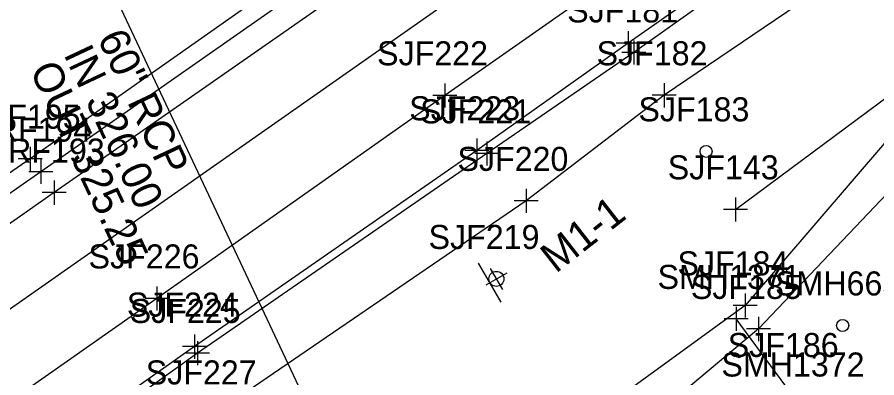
# Model space of a CAD drawing. Extents: x 941041 to 969446, y 397014 to 416764.
# Drawn here: x 953374.6 to 953517.5, y 404241 to 404301 of the extents above; entities that cross this region are included whole.
import ezdxf

# ---------------------------------------------------------------- set-up
doc = ezdxf.new("R2010")
doc.units = 0
for name, color, linetype in [('SURVEY - DRAINAGE - Area Shapes', 7, 'Continuous'), ('SURVEY - DRAINAGE - Pipes and Culverts', 7, 'Continuous'), ('SURVEY - DRAINAGE - Pipes and Culverts Text', 7, 'Continuous'), ('SURVEY - DTM - Breaklines', 7, 'Continuous'), ('SURVEY - DTM - Breaklines - Points - Locators', 7, 'Continuous'), ('SURVEY - DTM - Breaklines - Points - Numbers', 7, 'Continuous'), ('SURVEY - DTM - Spot Points - Locators', 7, 'Continuous'), ('SURVEY - DTM - Spot Points - Point Numbers', 7, 'Continuous'), ('SURVEY - TRAFFIC CONTROL - Signs - Points - Locators', 7, 'Continuous'), ('SURVEY - TRAFFIC CONTROL - Signs - Points - Numbers', 7, 'Continuous'), ('SURVEY - TRAFFIC CONTROL - Signs and Devices with Text', 7, 'Continuous'), ('SURVEY - TRANSPORTATION - Features', 7, 'Continuous'), ('SURVEY - TRANSPORTATION - Features - Points - Locators', 7, 'Continuous'), ('SURVEY - TRANSPORTATION - Features - Points - Numbers', 7, 'Continuous'), ('SURVEY - TRANSPORTATION - Roads', 7, 'Continuous'), ('SURVEY - TRANSPORTATION - Roads - Points - Locators', 7, 'Continuous'), ('SURVEY - TRANSPORTATION - Roads - Points - Numbers', 7, 'Continuous'), ('SURVEY - VEGETATION - Features - Points - Locators', 7, 'Continuous'), ('SURVEY - VEGETATION - Features - Points - Numbers', 7, 'Continuous'), ('SURVEY - VEGETATION - Features with Text', 7, 'Continuous')]:
    doc.layers.add(name, color=color, linetype=linetype)

msp = doc.modelspace()

# ---------------------------------------------------------------- linework, layer by layer
at = {"layer": 'SURVEY - DRAINAGE - Area Shapes'}
msp.add_lwpolyline([(954050.98, 404130.56), (953837.45, 404341.16), (953706.36, 404460.47), (953686.21, 404471.93), (953450.22, 404306.36), (952524.78, 403657.05)], dxfattribs=at)
at = {"layer": 'SURVEY - DRAINAGE - Pipes and Culverts'}
msp.add_line((953427.04, 404227.58), (953345.04, 404402.16), dxfattribs=at)
at = {"layer": 'SURVEY - DTM - Breaklines'}
for points in [[(953930.5, 404594.79), (953899.28, 404573.09), (953853.92, 404543.05), (953843.46, 404534.82), (953797.38, 404504.4), (953755.05, 404474.71), (953712.83, 404445.46), (953669.81, 404415.98), (953611.07, 404372.77), (953586.59, 404349.95), (953558.91, 404313.55), (953497.8, 404249.13), (953473.51, 404228.83), (953446.86, 404209.01), (953450.01, 404200.36), (953460.86, 404196.95), (953466.73, 404189.97)], [(953577.48, 404348.57), (953495.56, 404253.05), (953464.32, 404230.29), (953444.07, 404217.87), (953439.28, 404212.03), (953436.75, 404213.93), (953439.45, 404218.19), (953433.81, 404222.03), (953433.55, 404226), (953436.51, 404228.48), (953428.71, 404231.79), (953422.68, 404227.41), (953421.31, 404221.93), (953421, 404211.6), (953424.14, 404207.84), (953433.54, 404206.01), (953428.34, 404202.74), (953416.33, 404190.88), (953400.55, 404177.21), (953398.65, 404176.28)], [(953556.56, 404339.74), (953535.74, 404324.43), (953482.12, 404288), (953459.18, 404270.43), (953407.19, 404234.9), (953372.81, 404211.16)]]:
    msp.add_lwpolyline(points, dxfattribs=at)
at = {"layer": 'SURVEY - DTM - Breaklines - Points - Locators'}
for p, q in [((953482.12, 404290), (953482.12, 404286)), ((953484.12, 404288), (953480.12, 404288)), ((953459.18, 404272.43), (953459.18, 404268.43)), ((953461.18, 404270.43), (953457.18, 404270.43)), ((953495.56, 404255.05), (953495.56, 404251.05)), ((953497.56, 404253.05), (953493.56, 404253.05)), ((953497.8, 404251.13), (953497.8, 404247.13)), ((953499.8, 404249.13), (953495.8, 404249.13))]:
    msp.add_line(p, q, dxfattribs=at)
at = {"layer": 'SURVEY - DTM - Spot Points - Locators'}
for centre in [(953489.08, 404278.67), (953511.78, 404249.71)]:
    msp.add_circle(centre, 1, dxfattribs=at)
at = {"layer": 'SURVEY - TRAFFIC CONTROL - Signs - Points - Locators'}
for p, q in [((953455.95, 404258.44), (953452.48, 404256.44)), ((953453.21, 404259.17), (953455.22, 404255.71))]:
    msp.add_line(p, q, dxfattribs=at)
at = {"layer": 'SURVEY - TRAFFIC CONTROL - Signs and Devices with Text'}
msp.add_line((953455.03, 404253.58), (953451.28, 404260.07), dxfattribs=at)
msp.add_circle((953454.23, 404257.47), 1.25, dxfattribs=at)
at = {"layer": 'SURVEY - TRANSPORTATION - Features'}
for points in [[(953898.36, 404644.24), (953852.94, 404612.35), (953804.92, 404577.81), (953756.7, 404544.88), (953709.89, 404511.14), (953665.52, 404480.77), (953619.89, 404448.73), (953571.72, 404414.34), (953522.34, 404379.83), (953473.43, 404345.59), (953425.03, 404311.48), (953376.74, 404277.44), (953331.82, 404246.3), (953285.64, 404214.9), (953239.25, 404182.51), (953188.82, 404146.7), (953139.07, 404111.93), (953091.16, 404078.74), (953044.12, 404045.63), (952994.26, 404010.63)], [(953918.44, 404605.51), (953871.93, 404572.47), (953825.16, 404539.29), (953772.92, 404502.69), (953725.65, 404469.57), (953671.12, 404431.98), (953624.16, 404398.66), (953570.35, 404360.17), (953529.67, 404332.52), (953477.08, 404295.12), (953452.64, 404278.33), (953404.53, 404245.13), (953366.78, 404218.04)]]:
    msp.add_lwpolyline(points, dxfattribs=at)
at = {"layer": 'SURVEY - TRANSPORTATION - Features - Points - Locators'}
for p, q in [((953477.08, 404297.12), (953477.08, 404293.12)), ((953479.08, 404295.12), (953475.08, 404295.12)), ((953452.64, 404280.33), (953452.64, 404276.33)), ((953376.74, 404279.44), (953376.74, 404275.44)), ((953454.64, 404278.33), (953450.64, 404278.33)), ((953378.74, 404277.44), (953374.74, 404277.44)), ((953404.53, 404247.13), (953404.53, 404243.13)), ((953406.53, 404245.13), (953402.53, 404245.13))]:
    msp.add_line(p, q, dxfattribs=at)
at = {"layer": 'SURVEY - TRANSPORTATION - Roads'}
for points in [[(953900.62, 404641.5), (953855.22, 404609.45), (953807.02, 404575.69), (953758.99, 404542.01), (953711.75, 404508.82), (953668.09, 404478.06), (953621.84, 404445.43), (953573.82, 404411.95), (953523.8, 404377.02), (953475.53, 404343.33), (953426.53, 404308.93), (953378.51, 404275.3), (953333.58, 404243.9), (953288.55, 404212.21), (953241.33, 404178.78), (953191.41, 404143.85), (953140.87, 404108.55), (953093.94, 404075.57), (953046.11, 404041.98), (952997.22, 404007.75)], [(953902.72, 404637.94), (953857.45, 404606.12), (953808.81, 404571.8), (953761.55, 404538.67), (953714.57, 404505.72), (953670.63, 404474.8), (953623.35, 404441.74), (953576.1, 404408.57), (953525.65, 404373.27), (953477.92, 404339.82), (953428.19, 404304.98), (953380.75, 404271.81), (953335.05, 404239.73), (953288.64, 404207.14), (953242.9, 404175.1), (953193.89, 404141.01), (953142.58, 404104.93), (953096.45, 404072.54), (953047.38, 404038.13), (952999.67, 404004.66)], [(953912.33, 404615.61), (953865.26, 404582.3), (953819.57, 404550.16), (953767.19, 404513.26), (953718.04, 404478.91), (953664.43, 404441.32), (953617.26, 404408.04), (953563.31, 404370.48), (953522.75, 404341.92), (953471.46, 404306.09), (953445.64, 404287.99), (953397.8, 404254.2), (953360.06, 404227.77)], [(953917.37, 404606.65), (953870.42, 404573.23), (953824.67, 404541.2), (953771.76, 404503.86), (953724.46, 404470.77), (953670.22, 404432.73), (953623.39, 404399.95), (953569.03, 404361.75), (953528.76, 404333.61), (953476.11, 404296.68), (953450.98, 404278.84), (953404.05, 404246.19), (953365.7, 404219.13)]]:
    msp.add_lwpolyline(points, dxfattribs=at)
at = {"layer": 'SURVEY - TRANSPORTATION - Roads - Points - Locators'}
for p, q in [((953476.11, 404298.68), (953476.11, 404294.68)), ((953478.11, 404296.68), (953474.11, 404296.68)), ((953445.64, 404289.99), (953445.64, 404285.99)), ((953447.64, 404287.99), (953443.64, 404287.99)), ((953450.98, 404280.84), (953450.98, 404276.84)), ((953452.98, 404278.84), (953448.98, 404278.84)), ((953378.51, 404277.3), (953378.51, 404273.3)), ((953380.51, 404275.3), (953376.51, 404275.3)), ((953380.75, 404273.81), (953380.75, 404269.81)), ((953382.75, 404271.81), (953378.75, 404271.81)), ((953397.8, 404256.2), (953397.8, 404252.2)), ((953399.8, 404254.2), (953395.8, 404254.2)), ((953404.05, 404248.19), (953404.05, 404244.19)), ((953406.05, 404246.19), (953402.05, 404246.19))]:
    msp.add_line(p, q, dxfattribs=at)
at = {"layer": 'SURVEY - VEGETATION - Features - Points - Locators'}
for p, q in [((953493.95, 404271.02), (953493.95, 404267.02)), ((953495.95, 404269.02), (953491.95, 404269.02)), ((953494.06, 404252.8), (953494.06, 404248.8)), ((953496.06, 404250.8), (953492.06, 404250.8))]:
    msp.add_line(p, q, dxfattribs=at)
at = {"layer": 'SURVEY - VEGETATION - Features with Text'}
for points in [[(953493.95, 404269.02), (953619.99, 404362.71), (953670.1, 404398.06), (953723.08, 404433.68), (953766.8, 404464.07), (953851.45, 404519.5), (953865.64, 404528.02), (953910.6, 404557.74), (953935, 404570.53)], [(952615.41, 403645.7), (952663.71, 403647.1), (952767.16, 403724.79), (952854.64, 403814.73), (952901.03, 403821.23), (952972.41, 403873.85), (953072.36, 403942.71), (953151.12, 403998.66), (953210.95, 404036), (953255.08, 404074.19), (953321.18, 404112.82), (953394.86, 404155.77), (953420.13, 404180.6), (953476.58, 404225.47), (953504.82, 404236.22), (953494.06, 404250.8)]]:
    msp.add_lwpolyline(points, dxfattribs=at)

# ---------------------------------------------------------------- texts
at = {"layer": 'SURVEY - DRAINAGE - Pipes and Culverts Text'}
for s, p in [('60" RCP', (953387.85, 404297.5)), ('IN 326.00', (953382.23, 404294.85)), ('OUT 325.25', (953376.6, 404292.21))]:
    msp.add_text(s, height=4.998, rotation=295.1735, dxfattribs=at).set_placement(p)
at = {"layer": 'SURVEY - DTM - Breaklines - Points - Numbers'}
for s, p in [('SJF182', (953470.88, 404293)), ('SJF220', (953447.76, 404275.43)), ('SJF184', (953484.32, 404258.05)), ('SJF185', (953486.56, 404254.13)), ('SJF227', (953395.95, 404239.9))]:
    msp.add_text(s, height=4, dxfattribs=at).set_placement(p)
at = {"layer": 'SURVEY - DTM - Spot Points - Point Numbers'}
for s, p in [('SJF183', (953477.84, 404283.67)), ('SMH665', (953500.54, 404254.71)), ('SJF186', (953492.68, 404244.46))]:
    msp.add_text(s, height=4, dxfattribs=at).set_placement(p)
at = {"layer": 'SURVEY - TRAFFIC CONTROL - Signs - Points - Numbers'}
msp.add_text('SJF219', height=4, dxfattribs=at).set_placement((953442.96, 404262.44))
at = {"layer": 'SURVEY - TRAFFIC CONTROL - Signs and Devices with Text'}
msp.add_text('M1-1', height=4.998, rotation=38.0199, dxfattribs=at).set_placement((953464.1, 404258.28))
at = {"layer": 'SURVEY - TRANSPORTATION - Features - Points - Numbers'}
for s, p in [('SJF181', (953466, 404300.12)), ('SJF221', (953441.56, 404283.33)), ('SRF195', (953365.5, 404282.44)), ('SJF225', (953393.29, 404250.13))]:
    msp.add_text(s, height=4, dxfattribs=at).set_placement(p)
at = {"layer": 'SURVEY - TRANSPORTATION - Roads - Points - Numbers'}
for s, p in [('SJF222', (953434.4, 404292.99)), ('SJF223', (953439.74, 404283.84)), ('SRF194', (953367.27, 404280.3)), ('SRF193', (953369.51, 404276.81)), ('SJF226', (953386.45, 404259.2)), ('SJF224', (953392.81, 404251.19))]:
    msp.add_text(s, height=4, dxfattribs=at).set_placement(p)
at = {"layer": 'SURVEY - VEGETATION - Features - Points - Numbers'}
for s, p in [('SJF143', (953482.71, 404274.02)), ('SMH1371', (953481.02, 404255.8)), ('SMH1372', (953491.63, 404241.22))]:
    msp.add_text(s, height=4, dxfattribs=at).set_placement(p)

doc.saveas('drawing.dxf')
